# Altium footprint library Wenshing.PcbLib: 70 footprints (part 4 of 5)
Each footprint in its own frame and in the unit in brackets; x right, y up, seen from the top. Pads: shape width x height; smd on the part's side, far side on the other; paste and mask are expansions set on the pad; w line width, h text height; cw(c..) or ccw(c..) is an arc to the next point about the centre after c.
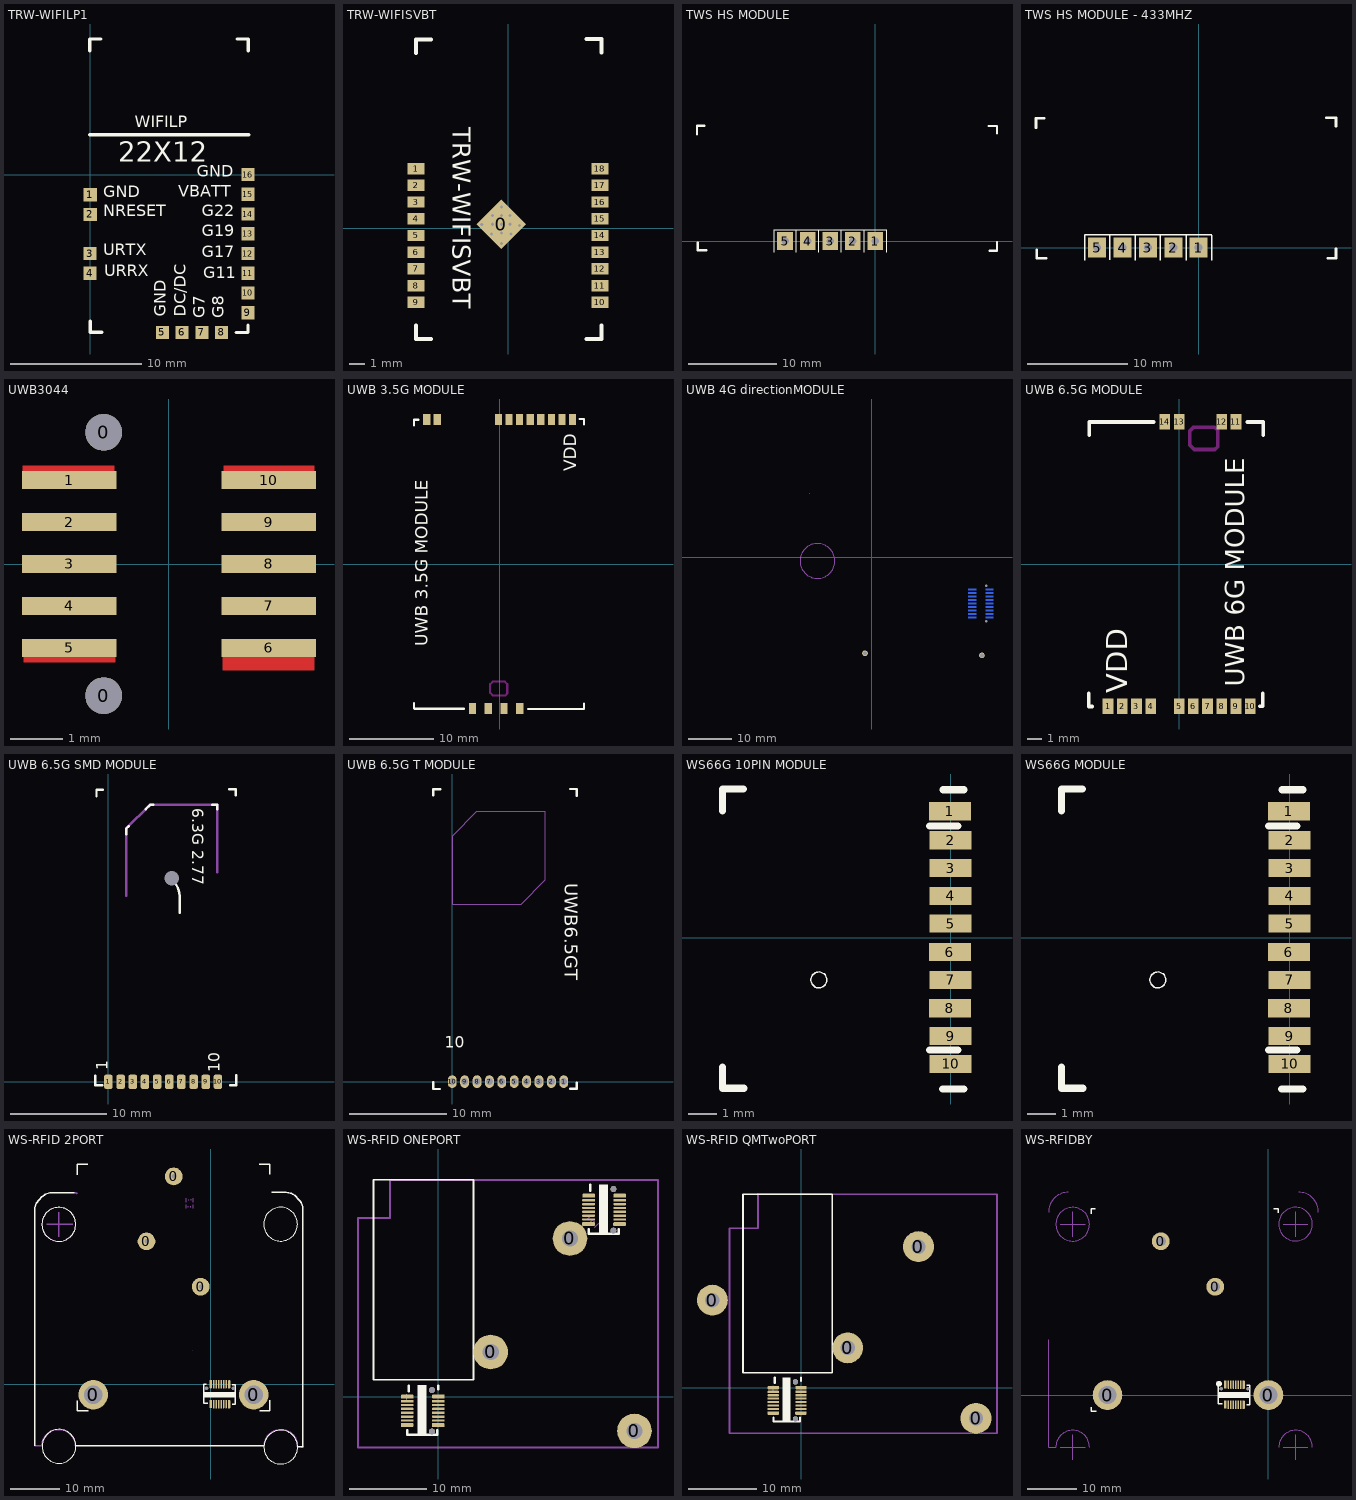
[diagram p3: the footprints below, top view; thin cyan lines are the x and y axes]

## TRW-WIFILP1 [mm] "WIFI+BT LOW POWER"
pads (16):
  rect 1x1 smd mask+0.102: 1(0.011,-1.528) 2(0.011,-3.028) 3(0,-6) 4(0,-7.5) 5(5.5,-12) 6(7,-12) 7(8.5,-12) 8(10,-12) 9(12,-10.5) 10(12,-9) 11(12,-7.5) 12(12,-6) 13(12,-4.5) 14(12,-3) 15(12,-1.5) 16(12,0)
Top Layer:
  lines w0.203: 0.065,-3.264 0.155,-3.174
Mid-Layer 2:
  lines w0.203: -0.048,-0.377 0.333,0.004 ; 0.017,-0.201 0.017,0.017
Top Overlay:
  lines w0.254: -0.014,3.02 12.051,3.02 ; -0.014,9.421 -0.014,10.31 0.824,10.31 ; 0.003,-11.139 0.003,-11.978 0.892,-11.978 ; 11.122,-12.003 12.011,-12.003 12.011,-11.455 ; 11.187,10.31 12.025,10.31 12.025,9.421
  text "WIFILP" at 3.4,3.3 h1.52
  text "NRESET" at 1.016,-3.464 h1.52
  text "22X12" at 2.159,0.991 h1.52
  text "GND" at 0.991,-2.042 h1.52
  text "URTX" at 1.016,-6.436 h1.52
  text "URRX" at 1.092,-8.036 h1.52
  text "G7" at 9.029,-10.922 h1.52
  text "G8" at 10.452,-10.922 h1.52
  text "DC/DC" at 7.583,-10.8 h1.52
  text "GND" at 6.042,-10.809 h1.52
  text "GND" at 8.1,-0.484 h1.52
  text "VBATT" at 6.701,-2 h1.52
  text "G22" at 8.5,-3.484 h1.52
  text "G19" at 8.5,-4.984 h1.52
  text "G17" at 8.5,-6.584 h1.52
  text "G11" at 8.6,-8.184 h1.52
3D body "TRW-WIFILP1.step": height 2.8, standoff -0.12, extent -0.125,-12.055 11.9,10.255

## TRW-WIFISVBT [mm] "WIFI +BT MODULE"
pads (32):
  round 0.45 hole 0.2 mask+0.102: 0(-1.727,0.229) 0(-1.079,-0.376) 0(-1.008,0.826) 0(-1.008,0.26) 0(-0.442,-1.013) 0(-0.442,-0.306) 0(-0.442,0.26) 0(-0.442,0.826) 0(-0.442,1.391) 0(0.123,0.26) 0(0.123,0.826) 0(0.194,-0.376) 0(0.76,0.189)
  rect 2.3x2.3 all layers, no hole rot 135 mask+0.08: 0(-0.442,0.26)
  rect 1.1x0.75 smd mask+0.102: 1(-6.05,3.922) 2(-6.05,2.822) 3(-6.05,1.722) 4(-6.05,0.622) 5(-6.05,-0.478) 6(-6.05,-1.578) 7(-6.05,-2.678) 8(-6.05,-3.778) 9(-6.05,-4.878) 10(6.05,-4.878) 11(6.05,-3.778) 12(6.05,-2.678) 13(6.05,-1.578) 14(6.05,-0.478) 15(6.05,0.622) 16(6.05,1.722) 17(6.05,2.822) 18(6.05,3.922)
Top Layer:
  region: -0.697,-0.421 -0.926,-0.542 -0.878,-0.275 -0.771,-0.207
  region: -0.595,-0.14 -0.824,-0.261 -0.75,-0.475 -0.643,-0.407
  region: -0.514,0.049 -0.529,0.032 -0.538,0.015 -0.541,0 -0.538,-0.015 -0.528,-0.029 -0.513,-0.042 -0.492,-0.054 -0.466,-0.066 -0.433,-0.076 -0.394,-0.086 -0.609,-0.155 -0.75,-0.475
  region: -0.717,-0.538 -0.702,-0.522 -0.689,-0.505 -0.679,-0.489 -0.67,-0.471 -0.664,-0.453 -0.659,-0.434 -0.657,-0.415 -0.657,-0.395 -0.658,-0.375 -0.662,-0.354 -0.398,-0.526 -0.421,-0.531 -0.463,-0.544 -0.483,-0.552 -0.502,-0.561 -0.52,-0.571 -0.537,-0.582 -0.554,-0.594 -0.57,-0.607 -0.584,-0.621
  lines w0.152: -0.716,1.382 -0.691,1.382 ; -0.442,-0.371 -0.442,-0.306 -0.442,-0.023 -0.442,0.26 ; 5.962,-1.49 6.05,-1.578
Top Overlay:
  lines w0.254: -6.045,-6.401 -6.045,-7.29 -5.055,-7.29 ; -6.045,11.532 -6.045,12.421 -5.055,12.421 ; 5.156,-7.29 6.147,-7.29 6.147,-6.401 ; 5.156,12.446 6.147,12.446 6.147,11.557
  text "TRW-WIFISVBT" at -4.033,6.645 h2.03
3D body "TRW-WIFISV.step": height 2.6, standoff -0.02, extent -6.045,-7.214 6.055,12.523

## TWS HS MODULE [mm] "RF transmitter module 315/371/433MHZ"
pads (5):
  rect 1.8x2 hole 0.8: 1(0,0) 2(-2.54,0) 3(-5.08,0) 4(-7.62,0) 5(-10.16,0)
Top Overlay:
  lines w0.127: -11.41,-1.27 -11.41,1.27 1.29,1.27 ; -8.9,-1.245 -8.9,1.295 ; -6.35,-1.27 -6.35,1.27 ; -3.825,-1.27 -3.825,1.27 ; -1.25,-1.27 -1.25,1.27 ; 1.29,-1.27 1.29,1.245
  lines w0.254: -20.117,12.045 -20.117,13.01 -19.279,13.01 ; -20.041,-0.198 -20.041,-1.036 -19.075,-1.036 ; 12.776,12.985 13.741,12.985 13.741,12.146 ; 12.903,-1.087 13.741,-1.087 13.741,-0.122
Bottom Overlay:
  lines w0.127: -11.41,-1.27 -11.41,1.245 ; -11.41,1.27 1.29,1.27 1.29,-1.27 ; -8.87,-1.27 -8.87,1.27 ; -6.295,-1.27 -6.295,1.27 ; -3.77,-1.27 -3.77,1.27 ; -1.22,-1.245 -1.22,1.295
3D body "tws-hsplus 372.step": height 15.29, standoff -7.51, extent -19.911,-1.118 13.661,12.979

## TWS HS MODULE - 433MHZ [mm] "RF transmitter module 315/371/433MHZ"
pads (5):
  rect 1.8x2 hole 0.8: 1(0,0) 2(-2.54,0) 3(-5.08,0) 4(-7.62,0) 5(-10.16,0)
Top Overlay:
  lines w0.127: -11.41,-1.27 -11.41,1.27 1.29,1.27 ; -8.9,-1.245 -8.9,1.295 ; -6.35,-1.27 -6.35,1.27 ; -3.825,-1.27 -3.825,1.27 ; -1.25,-1.27 -1.25,1.27 ; 1.29,-1.27 1.29,1.245
  lines w0.254: -16.281,11.994 -16.281,12.959 -15.443,12.959 ; -16.205,-0.249 -16.205,-1.087 -15.24,-1.087 ; 12.776,12.985 13.741,12.985 13.741,12.146 ; 12.903,-1.087 13.741,-1.087 13.741,-0.122
Bottom Overlay:
  lines w0.127: -11.41,-1.27 -11.41,1.245 ; -11.41,1.27 1.29,1.27 1.29,-1.27 ; -8.87,-1.27 -8.87,1.27 ; -6.295,-1.27 -6.295,1.27 ; -3.77,-1.27 -3.77,1.27 ; -1.22,-1.245 -1.22,1.295
3D body "TWS-HS MODILE.step": height 4.77, standoff -7.51, extent -16.353,-1.118 13.661,12.979

## UWB3044 [mm]
pads (12):
  round 0.7 hole 0.7: 0(-1.245,-2.508) 0(-1.245,2.508)
  rect 1.8x0.35 smd: 1(-1.9,1.6) 2(-1.9,0.8) 3(-1.9,0) 4(-1.9,-0.8) 5(-1.9,-1.6) 6(1.9,-1.6) 7(1.9,-0.8) 8(1.9,0) 9(1.9,0.8) 10(1.9,1.6)
Top Layer:
  rectangle: 1.016,-2.032 2.769,-1.752
  rectangle: -2.769,-1.88 -1.016,-1.6
  rectangle: -2.794,1.772 -1.041,1.873
  rectangle: 1.041,1.772 2.769,1.873
3D body "USB3044 V1.0.step": height 5.08, standoff 0.29, extent -3.315,-6.223 17.386,16.307

## UWB 3.5G MODULE [mm] "WENSHING UWB 3.5G MODULE"
pads (14):
  rect 0.85x1.3 smd mask+0.05: 1(8.625,17.094) 2(7.375,17.094) 3(6.125,17.094) 4(4.875,17.094) 5(3.625,17.094) 6(2.375,17.094) 7(1.125,17.094) 8(-0.125,17.094) 9(-7.375,17.094) 10(-8.625,17.094) 11(-3.216,-17.094) 12(-1.337,-17.094) 13(0.518,-17.094) 14(2.397,-17.094)
Top Overlay:
  lines w0.254: -10.141,16.416 -10.141,17.02 ; -10.116,-17.067 -10.116,-16.463 ; -10.091,17.071 -9.591,17.071 ; -10.065,-17.118 -4.198,-17.118 ; 3.397,-17.143 9.95,-17.143 ; 9.45,17.166 9.95,17.166 ; 10.001,-17.092 10.001,-16.489 ; 10.001,16.512 10.001,17.115
  text "VDD" at 9.594,10.951 h2.54
  text "UWB 3.5G MODULE" at -7.987,-9.726 h2.54
Keep-Out Layer:
  lines w0.254: -1.118,-15.24 -0.787,-15.57 0.66,-15.57 0.914,-15.316 0.914,-14.224 0.61,-13.919 -0.813,-13.919 -1.118,-14.224 -1.118,-15.24
3D body "UWB 3.5G MODULE.step": height 1.9, standoff 0.09, extent -10.051,-17.221 10.076,17.011

## UWB 4G directionMODULE [mm] "UWB 4G MODULE"
pads (22):
  round 1.3 / inner round 1.3 / far side round 3.6 hole 0.9: 0(-1.549,-22.149) 0(25.49,-22.64)
  round 0 hole 0.6: 0(26.481,-14.74) 0(26.481,-6.54)
  rect 1.8x0.35 smd far side: 1(27.231,-13.845) 2(27.231,-13.045) 3(27.231,-12.245) 4(27.231,-11.445) 5(27.231,-10.645) 6(27.231,-9.845) 7(27.231,-9.045) 8(27.231,-8.245) 9(27.231,-7.445) 10(23.231,-7.445) 11(23.231,-8.245) 12(23.231,-9.045) 13(23.231,-9.845) 14(23.231,-10.645) 15(23.231,-11.445) 16(23.231,-12.245) 17(23.231,-13.045) 18(23.231,-13.845)
Bottom Layer:
  region: 28.076,-7.185 26.349,-7.185 26.349,-7.286 28.076,-7.286
  region: 28.101,-14.017 26.348,-14.017 26.348,-14.119 28.101,-14.119
Top Overlay:
  lines w0.254: -14.402,14.781 -14.375,14.781
Bottom Overlay:
  lines w0.051: -40.373,16.269 cw(c-35.662,16.358) -35.75,21.069 ; -40.234,-19.482 ccw(c-35.522,-19.393) -35.433,-24.105 ; 23.231,-14.695 23.231,-15.17 24.006,-15.17 ; 23.231,-6.77 23.231,-6.12 23.256,-6.095 23.956,-6.095 ; 24.168,21.095 cw(c24.257,16.383) 28.969,16.472 ; 24.27,-24.117 ccw(c24.181,-19.406) 28.892,-19.317 ; 26.856,-15.195 27.231,-15.195 27.231,-14.395 27.206,-14.37 ; 26.881,-6.095 27.231,-6.095 27.231,-6.695
  lines w0.254: -38.65,-3.505 -38.65,14.781 -14.402,14.781 ; -38.65,-3.119 -38.65,-4.119 -36.65,-6.119 ; -36.906,-5.867 -27.965,-14.808 -6.401,-14.808 -6.401,6.807 -14.375,14.781
Mechanical 1:
  circle w0.001: c-12.522,-0.813 r4.027
3D body: height 3, standoff 0, extent 23.332,-14.04 24.431,-7.441
3D body: height 3, standoff 0, extent 26.032,-14.04 27.131,-7.441
3D body: height -5, standoff -9, extent -38.684,-14.783 -6.299,14.808
3D body: height 0.5, standoff 0, extent 27.231,-9.195 27.556,-8.895
3D body: height 0.5, standoff 0, extent 27.231,-8.395 27.556,-8.095
3D body: height 0.5, standoff 0, extent 22.893,-8.395 23.218,-8.095
3D body: height 0.5, standoff 0, extent 22.906,-9.195 23.231,-8.895
3D body: height 0.5, standoff 0, extent 27.231,-13.995 27.556,-13.695
3D body: height 0.5, standoff 0, extent 27.231,-13.195 27.556,-12.895
3D body: height 0.5, standoff 0, extent 27.231,-12.395 27.556,-12.095
3D body: height 0.5, standoff 0, extent 27.231,-11.595 27.556,-11.295
3D body: height 0.5, standoff 0, extent 27.231,-10.795 27.556,-10.495
3D body: height 0.5, standoff 0, extent 27.231,-9.995 27.556,-9.695
3D body: height 0.5, standoff 0, extent 27.231,-7.595 27.556,-7.295
3D body: height 0.5, standoff 0, extent 22.906,-7.595 23.231,-7.295
3D body: height 0.5, standoff 0, extent 22.906,-9.995 23.231,-9.695
3D body: height 0.5, standoff 0, extent 22.906,-10.795 23.231,-10.495
3D body: height 0.5, standoff 0, extent 22.906,-11.595 23.231,-11.295
3D body: height 0.5, standoff 0, extent 22.906,-12.395 23.231,-12.095
3D body: height 0.5, standoff 0, extent 22.906,-13.195 23.231,-12.895
3D body: height 0.5, standoff 0, extent 22.906,-13.995 23.231,-13.695

## UWB 6.5G MODULE [mm] "WENSHING ELECTRO"
pads (14):
  rect 0.75x1.1 smd mask+0.05: 1(-5,-10) 2(-4,-10) 3(-3,-10) 4(-2,-10) 5(0,-10) 6(1,-10) 7(2,-10) 8(3,-10) 9(4,-10) 10(5,-10) 11(4,10) 12(3,10) 13(0,10) 14(-1,10)
Mid-Layer 2:
  lines w0.305: -4,-10 -4,-9.602
Top Overlay:
  lines w0.254: -6.346,-9.111 -6.346,-10.025 -6.118,-10.025 ; -6.321,9.075 -6.321,9.99 -1.774,9.99 ; 4.804,9.99 5.922,9.99 5.922,9.075 ; 5.668,-10 5.897,-10 5.897,-9.086
  text "VDD" at -3.153,-9.107 h2.54
  text "UWB 6G MODULE" at 5.031,-8.628 h2.29
Keep-Out Layer:
  lines w0.254: 0.762,8.357 1.067,8.052 2.515,8.052 2.718,8.255 2.718,9.398 2.489,9.627 1.016,9.627 0.762,9.373 0.762,8.357
3D body: height 22.2, standoff 1, extent -8.898,8.614 12.302,8.814
3D body "UWB 6G MODULE.step": height 1.7, standoff 0.09, extent -6.473,-10.247 6.025,10.008

## UWB 6.5G SMD MODULE [mm] "WENSHING ELECTRO 貼片型天線內置"
pads (11):
  rrect50% 0.9x1.5 smd mask+0.05: 1(0,0) 2(1.27,0) 3(2.54,0) 4(3.81,0) 5(5.08,0) 6(6.35,0) 7(7.62,0) 8(8.89,0) 9(10.16,0) 10(11.43,0)
  round 0 hole 1.5: 3(6.6,21.265)
Top Overlay:
  lines w0.254: -1.372,0.635 -1.372,-0.356 -0.66,-0.356 ; -1.245,29.794 -1.245,30.505 -0.61,30.505 ; 1.85,25.863 1.85,26.422 ; 3.882,28.454 4.339,28.911 4.67,28.911 ; 6.566,21.26 cw(c4.42,19.114) 7.455,19.114 ; 7.455,17.638 7.455,19.228 ; 10.816,28.911 11.35,28.911 11.35,28.428 ; 12.598,30.531 13.31,30.531 13.31,29.896 ; 12.713,-0.381 13.348,-0.381 13.348,0.686 ; 1.85,26.422 2.13,26.701 1.85,26.422
  text "10" at 12.019,1.016 h2
  text "1" at 0.356,1.219 h2
  text "6.3G 2.77" at 8.322,28.565 h2
Mechanical 1:
  lines w0.254: 1.853,19.406 1.853,26.428 4.332,28.907 11.354,28.907 11.354,21.885
Mechanical 2:
  lines w0.013: 1.853,19.406 1.853,26.428 4.332,28.907 11.354,28.907 11.354,21.885
3D body "Copy of UWB 6.5G direction SMD MODULE.step": height 3, standoff -0.15, extent -1.331,-0.737 13.36,30.734
3D body: height 1, standoff 0, extent 1.676,17.754 11.176,27.255

## UWB 6.5G T MODULE [mm] "WENSHING ELECTRO 貼片型天線內置"
pads (10):
  oval 0.9x1.3 hole 0.7 mask+0.05: 1(11.43,0) 2(10.16,0) 3(8.89,0) 4(7.62,0) 5(6.35,0) 6(5.08,0) 7(3.81,0) 8(2.54,0) 9(1.27,0) 10(0,0)
Top Overlay:
  lines w0.254: -1.93,-0.051 -1.93,-0.762 -1.295,-0.762 ; -1.93,29.312 -1.93,29.947 -1.219,29.947 ; 12.065,-0.737 12.776,-0.737 12.776,-0.102 ; 12.116,29.972 12.751,29.972 12.751,29.261
  text "UWB6.5GT" at 11.073,20.32 h2.29
  text "10" at -0.762,3.069 h2
Mechanical 2:
  lines w0.013: 0.029,18.181 0.029,25.203 2.507,27.682 9.529,27.682 9.529,20.66 7.05,18.181 0.029,18.181
3D body: height 2, standoff 0, extent 0.029,18.181 9.529,27.682
3D body "Connector 10pin 1.27mm.stp": height 4.4, standoff -0.3, extent -1.016,-1.905 12.084,2.095

## WS66G 10PIN MODULE [mm] "66GHZ RF MODULE"
pads (10):
  rect 1.5x0.65 smd: 1(-0.025,4.521) 2(0,3.48) 3(0,2.489) 4(0,1.499) 5(0,0.508) 6(-0.025,-0.508) 7(0,-1.499) 8(-0.025,-2.515) 9(0,-3.505) 10(0,-4.496)
Top Overlay:
  circle w0.051: c-4.7,-1.5 r0.284
  lines w0.254: -8.14,-4.614 -8.14,-5.364 -7.365,-5.364 ; -8.14,4.536 -8.14,5.311 -7.39,5.311 ; -0.745,-4.004 0.255,-4.004 ; -0.745,3.996 0.255,3.996 ; -0.292,-5.392 0.483,-5.392 ; -0.267,5.283 0.483,5.283
Bottom Overlay:
3D body "A111_dark v1.step": height 0.51, standoff 0, extent -7.402,-4.147 -1.902,1.057

## WS66G MODULE [mm] "66GHZ RF MODULE"
pads (10):
  rect 1.5x0.65 smd: 1(-0.025,4.521) 2(0,3.48) 3(0,2.489) 4(0,1.499) 5(0,0.508) 6(-0.025,-0.508) 7(0,-1.499) 8(-0.025,-2.515) 9(0,-3.505) 10(0,-4.496)
Top Overlay:
  circle w0.051: c-4.7,-1.5 r0.284
  lines w0.254: -8.14,-4.614 -8.14,-5.364 -7.365,-5.364 ; -8.14,4.536 -8.14,5.311 -7.39,5.311 ; -0.745,-4.004 0.255,-4.004 ; -0.745,3.996 0.255,3.996 ; -0.292,-5.392 0.483,-5.392 ; -0.267,5.283 0.483,5.283
Bottom Overlay:
3D body "A111_dark v1.step": height 0.51, standoff 0, extent -7.402,-4.147 -1.902,1.057
3D body "66GHZ MODULE3.step": height 2, standoff -0.04, extent -8.1,-5.394 0.476,5.217

## WS-RFID 2PORT [mil]
pads (23):
  round 236.22 hole 145.67: 0(-936.96,-83.19) 0(342.57,-83.19)
  round 141.73 / inner round 51.18 / far side round 51.18 hole 35.43: 0(-513.02,1139.76) 0(-80.46,778.07)
  round 141.73 hole 35.43: 0(-295.46,1658.07)
  round 0 hole 30 mask+7.87: 0(-33.3,-32.76)
  round 24 hole 30 mask+7.87: 0(179.3,-32.76)
  rrect50% 20x65 smd mask+2: 1(0,0) 8(146,-1) 9(146,-160) 16(0,-159)
  rrect50% 12x65 smd mask+2: 2(23.79,-0.32) 3(43.47,-0.32) 4(63.16,-0.32) 5(82.84,-0.32) 6(102.53,-0.32) 7(122.21,-0.32) 10(122.21,-159.68) 11(102.53,-159.68) 12(82.84,-159.68) 13(63.16,-159.68) 14(43.47,-159.68) 15(23.79,-159.68)
Top Overlay:
  circle w2: c-1212.57,1275.52 r134.84
  circle w2: c-1211.46,-495.93 r134.84
  circle w2: c558.54,-501.93 r134.84
  circle w2: c557.54,1277.07 r134.84
  region: -56.92,-60.31 -56.92,-107.56 191.11,-107.56 191.11,-60.31
  lines w10: -1405.46,-490.51 -1405.46,1386.07 cw(c-1284.75,1386.07) -1370.11,1471.43 -1347.82,1493.72 cw(c-1262.46,1408.36) -1262.46,1529.07 -1087.61,1529.07 ; -1077.05,-492.93 424.54,-492.93 ; -1064.81,-130.69 -1064.81,-211.43 ; -1064.05,1671.61 -1064.05,1756.69 ccw(c-1064.37,1756.69) -1064.15,1756.92 ; -983.41,1756.92 -1064.15,1756.92 ; -979.51,-211.33 -1064.59,-211.33 ccw(c-1064.59,-211.65) -1064.81,-211.43 ; 385.85,1755.29 470.93,1755.29 ccw(c470.93,1755.61) 471.16,1755.39 ; 390.39,-211.95 471.13,-211.95 ; 471.03,-126.64 471.03,-211.72 ccw(c471.35,-211.72) 471.13,-211.95 ; 471.16,1674.65 471.16,1755.39 ; 488.54,1530.07 602.69,1530.07 cw(c602.69,1424.23) 677.54,1499.07 699.18,1477.43 cw(c613.82,1392.07) 734.54,1392.07 734.54,-501.32 ; 693.95,-498.93 726.04,-498.93 ; -1064.81,-211.43 -1064.81,-151.27 ; -1064.81,-151.26 ccw(c-1064.81,-151.26) -1064.81,-151.26 ; -1064.81,-151.27 -1064.81,-151.26 ; -1064.15,1756.92 -1003.99,1756.92 ; -1003.98,1756.91 ccw(c-1003.98,1756.91) -1003.98,1756.91 ; -1003.99,1756.92 -1003.98,1756.91 ; 410.96,-211.94 ccw(c410.96,-211.94) 410.96,-211.94 ; 410.97,-211.95 471.13,-211.95 ; 410.96,-211.94 410.97,-211.95 ; 471.15,1695.22 ccw(c471.15,1695.22) 471.15,1695.22 ; 471.15,1695.22 471.16,1695.23 471.16,1755.39
  lines w11.81: -37.24,-1.26 -56.92,-1.26 -56.92,-150.87 -25.43,-150.87 ; 171.43,-158.74 195.04,-158.74 195.04,-5.2 171.43,-5.2
Bottom Overlay:
  lines w3.94: -1004.09,100.2 -1004.09,52.56 -956.84,52.56
Mechanical 2:
  circle w2: c-1212.46,1275.07 r134.84
  lines w10: -1405.46,-490.51 ccw(c-1402.05,-490.51) -1404.46,-492.93 -1348.46,-492.93 cw(c-1227.75,-492.93) -1313.11,-407.57 -1303.82,-398.28 cw(c-1218.46,-483.64) -1218.46,-362.93 -1207.46,-362.93 cw(c-1207.46,-483.64) -1122.11,-398.28 -1114.82,-405.57 cw(c-1200.18,-490.93) -1079.46,-490.93 -1079.46,-491.93 ccw(c-1077.05,-489.51) -1077.05,-492.93 ; -1310.46,1276.07 ccw(c-1308.05,1278.49) -1308.05,1275.07 -1102.46,1275.07 ; -1213.46,1176.07 ccw(c-1215.88,1178.49) -1212.46,1178.49 -1212.46,1372.07 ; -1087.61,1529.07 cw(c-1087.61,1494.93) -1063.46,1519.07 ; 424.54,-492.93 cw(c545.25,-492.93) 459.89,-407.57 468.18,-399.28 cw(c553.54,-484.64) 553.54,-363.93 565.54,-363.93 cw(c565.54,-484.64) 650.89,-399.28 656.18,-404.57 cw(c570.82,-489.93) 691.54,-489.93 691.54,-499.93 cw(c693.95,-502.34) 693.95,-498.93 ; 726.04,-498.93 cw(c726.04,-511.73) 735.1,-502.68 cw(c736.46,-501.32) 734.54,-501.32
Mechanical 3:
  lines w3.94: -149.13,267.37 -149.13,268.77
Mechanical 15:
  lines w1: -196.52,1402.32 -196.52,1433.82 ; -196.52,1452.32 -196.52,1483.82 ; -141.41,1402.32 -141.41,1433.82 ; -141.41,1452.32 -141.41,1483.82
  lines w1.97: -178.96,1412.07 -178.96,1418.07 ; -178.96,1468.07 -178.96,1473.07 ; -158.96,1413.07 -158.96,1418.07 ; -158.96,1468.07 -158.96,1474.07
3D body "rfidTM2PORT V1.1.step": height -169.29, standoff -218.33, extent -1063.59,-219.12 481.86,1756.35
3D body "SMA-PCB 90.STEP": height -11.81, standoff -250, extent 172.25,1609.89 408.47,2145.33
3D body "SMA-PCB 90.STEP": height -11.81, standoff -250, extent -197.88,1607.43 38.34,2142.86
3D body "Connector 16pin 0.5mm.stp": height -78.74, standoff -161.42, extent -56.92,-184.33 202.92,24.33
3D body "大黃散熱片.stp": height 248.03, standoff 169.29, extent -1393.47,-504.42 752.2,1522.2

## WS-RFID ONEPORT [mil]
pads (39):
  round 30 hole 30: 0(-32.76,-179.3) 0(-32.76,33.3) 0(895.76,849.24) 0(895.76,1061.84)
  round 177.17 hole 82.68 mask+4: 0(267.71,228.1) 0(673.67,809.01) 0(1003.67,-175.99)
  rrect50% 65x20 smd mask+2: 0(768.51,882.54) 0(769.51,1028.54) 0(927.51,882.54) 0(928.51,1028.54) 1(0,0) 8(-1,-146) 9(-160,-146) 16(-159,0)
  rrect50% 65x12 smd mask+2: 0(768.84,906.33) 0(768.84,926.02) 0(768.84,945.7) 0(768.84,965.39) 0(768.84,985.07) 0(768.84,1004.76) 0(928.19,906.33) 0(928.19,926.02) 0(928.19,945.7) 0(928.19,965.39) 0(928.19,985.07) 0(928.19,1004.76) 2(-0.32,-23.79) 3(-0.32,-43.47) 4(-0.32,-63.16) 5(-0.32,-82.84) 6(-0.32,-102.53) 7(-0.32,-122.21) 10(-159.68,-122.21) 11(-159.68,-102.53) 12(-159.68,-82.84) 13(-159.68,-63.16) 14(-159.68,-43.47) 15(-159.68,-23.79)
Top Overlay:
  region: -60,58.43 -107.25,58.43 -107.25,-189.6 -60,-189.6
  region: 868.2,1085.46 820.96,1085.46 820.96,837.43 868.2,837.43
  lines w10: -332.81,86 -332.81,1109.62 179,1109.62 179,86 -332.81,86
  lines w11.81: -158.74,-171.43 -158.74,-195.05 -5.2,-195.05 -5.2,-171.43 ; -150.87,25.43 -150.87,56.92 ; -1.26,37.24 -1.26,56.92 ; 769.77,857.12 769.77,833.5 923.32,833.5 923.32,857.12 ; 777.65,1053.97 777.65,1085.46
Top Solder:
  circle w51.18: c267.71,228.1 r19.68
  circle w51.18: c673.67,809.01 r19.68
  circle w51.18: c1003.67,-175.99 r19.68
  lines w39.37: 197.08,252.74 ccw(c267.71,228.1) 198.6,199.48 ; 239.09,297.21 cw(c267.71,228.1) 292.35,298.73 ; 243.07,157.47 ccw(c267.71,228.1) 296.34,158.99 ; 336.82,256.73 cw(c267.71,228.1) 338.34,203.46 ; 603.04,833.65 ccw(c673.67,809.01) 604.56,780.38 ; 645.05,878.12 cw(c673.67,809.01) 698.31,879.64 ; 649.03,738.38 ccw(c673.67,809.01) 702.3,739.9 ; 742.78,837.63 cw(c673.67,809.01) 744.3,784.37 ; 933.04,-151.35 ccw(c1003.67,-175.99) 934.56,-204.62 ; 975.05,-106.88 cw(c1003.67,-175.99) 1028.31,-105.36 ; 979.03,-246.62 ccw(c1003.67,-175.99) 1032.3,-245.1 ; 1072.78,-147.37 cw(c1003.67,-175.99) 1074.3,-200.63
Bottom Solder:
  circle w70.87: c1003.67,-175.99 r29.53
  circle w70.87: c673.67,809.01 r29.53
  circle w70.87: c267.71,228.1 r29.53
Mechanical 1:
  lines w10: -411.33,-260.99 1124.11,-260.99 1124.11,1109.01 -247.01,1109.01 -247.01,914.01 -411.33,914.01 -411.33,-260.99
Mechanical 15:
  lines w1: -160.77,-20.74 -160.77,10.76 ; 760.68,904.73 782.95,927 ; 799.65,865.76 821.92,888.03 ; 930.23,-221.74 930.23,-190.24
  lines w3.94: 780.69,894.26 793.42,906.99 ; 788.47,886.48 801.2,899.21
3D body "CAP0402C.STEP": height 13.98, standoff 0, extent 770.71,875.78 813.3,918.37
3D body: height 3.94, standoff -157.48, extent 769.77,829.56 927.25,1093.34
3D body: height 0, standoff -196.85, extent -158.74,-198.98 -1.26,64.8
3D body "rfid1port v2.2.step": height 224.58, standoff -36.43, extent -411.42,-262.72 1124.02,1107.28

## WS-RFID QMTwoPORT [mil]
pads (22):
  round 177.17 hole 82.68 mask+4: 0(-508.53,501.91) 0(267.71,228.1) 0(673.67,809.01) 0(1003.67,-175.99)
  round 30 hole 30: 0(-32.76,-179.3) 0(-32.76,33.3)
  rrect50% 65x20 smd mask+2: 1(0,0) 8(-1,-146) 9(-160,-146) 16(-159,0)
  rrect50% 65x12 smd mask+2: 2(-0.32,-23.79) 3(-0.32,-43.47) 4(-0.32,-63.16) 5(-0.32,-82.84) 6(-0.32,-102.53) 7(-0.32,-122.21) 10(-159.68,-122.21) 11(-159.68,-102.53) 12(-159.68,-82.84) 13(-159.68,-63.16) 14(-159.68,-43.47) 15(-159.68,-23.79)
Top Overlay:
  region: -60,58.43 -107.25,58.43 -107.25,-189.6 -60,-189.6
  lines w10: -332.81,86 179,86 179,1109.62 -332.81,1109.62 -332.81,86
  lines w11.81: -158.74,-171.43 -158.74,-195.05 -5.2,-195.05 -5.2,-171.43 ; -150.87,25.43 -150.87,56.92 ; -1.26,37.24 -1.26,56.92
Top Solder:
  circle w51.18: c-508.53,501.91 r19.68
  circle w51.18: c1003.67,-175.99 r19.68
  circle w51.18: c673.67,809.01 r19.68
  circle w51.18: c267.71,228.1 r19.68
  lines w39.37: -579.16,526.55 ccw(c-508.53,501.91) -577.64,473.29 ; -537.16,571.02 cw(c-508.53,501.91) -483.89,572.54 ; -533.17,431.29 ccw(c-508.53,501.91) -479.91,432.81 ; -439.42,530.54 cw(c-508.53,501.91) -437.9,477.27 ; 197.08,252.74 ccw(c267.71,228.1) 198.6,199.48 ; 239.09,297.21 cw(c267.71,228.1) 292.35,298.73 ; 243.07,157.47 ccw(c267.71,228.1) 296.34,158.99 ; 336.82,256.73 cw(c267.71,228.1) 338.34,203.46 ; 603.04,833.65 ccw(c673.67,809.01) 604.56,780.38 ; 645.05,878.12 cw(c673.67,809.01) 698.31,879.64 ; 649.03,738.38 ccw(c673.67,809.01) 702.3,739.9 ; 742.78,837.63 cw(c673.67,809.01) 744.3,784.37 ; 933.04,-151.35 ccw(c1003.67,-175.99) 934.56,-204.62 ; 975.05,-106.88 cw(c1003.67,-175.99) 1028.31,-105.36 ; 979.03,-246.62 ccw(c1003.67,-175.99) 1032.3,-245.1 ; 1072.78,-147.37 cw(c1003.67,-175.99) 1074.3,-200.63
Bottom Solder:
  circle w70.87: c267.71,228.1 r29.53
  circle w70.87: c673.67,809.01 r29.53
  circle w70.87: c1003.67,-175.99 r29.53
  circle w70.87: c-508.53,501.91 r29.53
Mechanical 1:
  lines w10: -411.33,-260.99 -411.33,914.01 -247.01,914.01 -247.01,1109.01 1124.11,1109.01 1124.11,-260.99 -411.33,-260.99
Mechanical 15:
  lines w1: -160.77,-20.74 -160.77,10.76 ; 930.23,-221.74 930.23,-190.24
3D body: height 0, standoff -196.85, extent -158.74,-198.98 -1.26,64.8
3D body "QM100雙天線.step": height 239.96, standoff -36.32, extent -796.68,-262.71 1126.66,1321.97

## WS-RFIDBY [mil] "RFID 大黃用"
pads (22):
  round 236.22 hole 141.73: 0(-1279.53,0) 0(0,0)
  round 141.73 hole 78.74: 0(-855.59,1222.95) 0(-423.03,861.26)
  rrect50% 20x65 smd mask+2: 1(-342.57,83.19) 8(-196.57,82.19) 9(-196.57,-76.81) 16(-342.57,-75.81)
  rrect50% 12x65 smd mask+2: 2(-318.78,82.87) 3(-299.09,82.87) 4(-279.41,82.87) 5(-259.72,82.87) 6(-240.04,82.87) 7(-220.35,82.87) 10(-220.35,-76.49) 11(-240.04,-76.49) 12(-259.72,-76.49) 13(-279.41,-76.49) 14(-299.09,-76.49) 15(-318.78,-76.49)
  round 24 hole 25.59 mask+7.87: 21(-375.87,50.43) 21(-163.27,50.43)
Mid-Layer 3:
  circle w0.5: c-675.1,470.92 r108.27
  region: 397.73,1830.52 437.1,1823.96 437.1,1837.08
  region: -1747.94,1830.52 -1708.57,1823.96 -1708.57,1837.08
  lines w0.5: -1747.94,439.43 -1682.98,439.43 -1682.98,502.42 -1747.94,502.42 -1747.94,1455.17 ; -1747.94,1457.63 -1747.94,1835.44 ; -1629.83,1830.52 -859.75,1830.52 ; -1590.46,1612.65 240.25,1612.65 ; -1422.42,-413.97 -1422.42,-512.39 -1117.42,-512.39 -1117.42,-359.79 -540.65,-359.79 -540.65,-512.39 82,-512.39 82,-413.97 ; -773.53,470.92 -576.68,470.92 ; -675.1,372.5 -675.1,569.35 ; -490.46,1830.52 279.62,1830.52 ; 349.72,-413.97 397.73,-413.97 397.73,439.43 332.77,439.43 332.77,502.42 397.73,502.42 397.73,1455.17 ; 397.73,1457.63 397.73,1835.44
  text "54.50" at -492.98,1771.46 h118.11
Mid-Layer 11:
  circle w0.25: c397.73,1455.17 r0.12
  circle w0.25: c-1747.94,1455.17 r0.12
  circle w0.25: c-1747.94,1830.52 r0.12
  circle w0.25: c240.25,1612.65 r0.12
  circle w0.25: c82,-512.39 r0.12
Top Overlay:
  circle w23.62: c-393.8,89.92 r11.81
  region: -399.49,22.87 -399.49,-24.37 -151.46,-24.37 -151.46,22.87
  lines w10: -1409.03,1443.26 -1409.03,1481.26 -1378.03,1481.26 ; -1408.03,-97.74 -1408.03,-128.74 -1370.03,-128.74 ; 40.97,1480.26 78.97,1480.26 78.97,1449.26
  lines w11.81: -399.49,81.93 -399.49,-67.68 -367.99,-67.68 ; -171.14,-75.55 -147.52,-75.55 -147.52,77.99 -171.14,77.99
Mechanical 3:
  circle w0.5: c-1556.28,1358.03 r133.86
  circle w0.5: c215.86,1359.03 r133.86
  lines w0.5: -1747.94,439.43 -1747.94,-413.97 -1690.14,-413.97 cw(c-1556.28,-413.97) -1422.42,-413.97 ; -1747.94,1455.17 cw(c-1590.46,1455.17) -1590.46,1612.65 ; -1654.71,-413.97 -1457.86,-413.97 ; -1654.71,1358.03 -1457.86,1358.03 ; -1556.28,-512.39 -1556.28,-315.54 ; -1556.28,1259.61 -1556.28,1456.46 ; 82,-413.97 cw(c215.86,-413.97) 349.72,-413.97 ; 117.44,-413.97 314.29,-413.97 ; 117.44,1359.03 314.29,1359.03 ; 215.86,-512.39 215.86,-315.54 ; 215.86,1260.61 215.86,1457.46 ; 240.25,1612.65 cw(c240.25,1455.17) 397.73,1455.17
3D body: height 17.72, standoff 0, extent -657.72,692.32 -618.35,755.32
3D body "RFIDBY RF2.step": height -7.87, standoff -275.59, extent -1748.24,-419.38 397.43,1607.25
